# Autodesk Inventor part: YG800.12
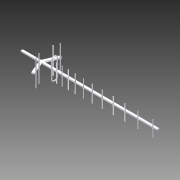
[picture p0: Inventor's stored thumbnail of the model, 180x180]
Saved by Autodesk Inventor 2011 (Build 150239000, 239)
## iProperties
Created: 2014-03
Part Number: YG800.12
Document SubType Name: Modeling
Designer: Evgeny
Density: 1 g/cm^3
Author: Evgeny
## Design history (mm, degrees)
sketch "Эскиз1"
  geometry: C1 r 4 at (0, 0); C2 r 3 at (0, 0); C3 r 4 at (80, 0); C4 r 3 at (80, 0); C5 r 4 at (125, 0); C6 r 3 at (125, 0); C7 r 4 at (172, 0); C8 r 3 at (172, 0); C9 r 4 at (226, 0); C10 r 3 at (226, 0); C11 r 4 at (288.5, 0); C12 r 3 at (288.5, 0); C13 r 4 at (359.5, 0); C14 r 3 at (359.5, 0); C15 r 4 at (438.5, 0); C16 r 3 at (438.5, 0); C17 r 4 at (525.5, 0); C18 r 3 at (525.5, 0); C19 r 4 at (725.5, 0); C20 r 3 at (725.5, 0); C21 r 4 at (621.5, 0); C22 r 3 at (621.5, 0); C23 r 4 at (35, 95); C24 r 3 at (35, 95); C25 r 4 at (35, -95); C26 r 3 at (35, -95); C27 r 3 at (837.5, 0); C28 r 4 at (837.5, 0); C29 r 3 at (969, 0); C30 r 4 at (969, 0); 1 further point
  constraints: 30 centre point, 16 coincident
  dimensions: "d0" = 8 diameter of C1; "d1" = 6 diameter of C2; "d2" = 8 diameter of C3; "d3" = 6 diameter of C4; "d4" = 8 diameter of C5; "d5" = 6 diameter of C6; "d6" = 8 diameter of C7; "d7" = 6 diameter of C8; "d8" = 8 diameter of C9; "d9" = 6 diameter of C10; "d10" = 8 diameter of C11; "d11" = 6 diameter of C12; "d12" = 8 diameter of C13; "d13" = 6 diameter of C14; "d14" = 8 diameter of C15; "d15" = 6 diameter of C16; "d16" = 8 diameter of C17; "d17" = 6 diameter of C18; "d18" = 8 diameter of C19; "d19" = 6 diameter of C20; "d20" = 8 diameter of C21; "d21" = 6 diameter of C22; "d22" = 8 diameter of C23; "d23" = 6 diameter of C24; "d24" = 8 diameter of C25; "d25" = 6 diameter of C26; "d26" = 35 horizontal distance of point (0, 0) C23.centre; "d27" = 35 horizontal distance of C25.centre C1.centre; "d28" = 95 vertical distance of point (0, 0) C24.centre; "d29" = 95 vertical distance of point (0, 0) C25.centre; "d30" = 80 distance of C3.centre point (0, 0); "d31" = 125 distance of C5.centre point (0, 0); "d32" = 172 distance of C7.centre point (0, 0); "d33" = 226 distance of point (0, 0) C9.centre; "d34" = 288.5 distance of point (0, 0) C11.centre; "d35" = 359.5 distance of point (0, 0) C13.centre; "d36" = 438.5 distance of point (0, 0) C15.centre; "d37" = 525.5 distance of point (0, 0) C17.centre; "d38" = 621.5 distance of point (0, 0) C21.centre; "d39" = 725.5 distance of point (0, 0) C19.centre; "d40" = 8 diameter of C28; "d41" = 6 diameter of C27; "d42" = 8 diameter of C30; "d43" = 6 diameter of C29; "d46" = 837.5 distance of point (0, 0) C28.centre; "d47" = 969 distance of point (0, 0) C30.centre
extrude "Выдавливание2" join sketch "Эскиз1" stored distance "d50" = 159; taper "d51" = 0 deg
extrude "Выдавливание3" join sketch "Эскиз1" stored distance "d52" = 156.5; taper "d53" = 0 deg
extrude "Выдавливание4" join sketch "Эскиз1" stored distance "d54" = 154; taper "d55" = 0 deg
extrude "Выдавливание5" join sketch "Эскиз1" stored distance "d56" = 151.5; taper "d57" = 0 deg
extrude "Выдавливание6" join sketch "Эскиз1" stored distance "d58" = 149; taper "d59" = 0 deg
extrude "Выдавливание7" join sketch "Эскиз1" stored distance "d60" = 146; taper "d61" = 0 deg
extrude "Выдавливание8" join sketch "Эскиз1" stored distance "d62" = 144; taper "d63" = 0 deg
extrude "Выдавливание9" join sketch "Эскиз1" stored distance "d64" = 141; taper "d65" = 0 deg
extrude "Выдавливание10" join sketch "Эскиз1" stored distance "d66" = 138; taper "d67" = 0 deg
extrude "Выдавливание11" join sketch "Эскиз1" stored distance "d68" = 135; taper "d69" = 0 deg
extrude "Выдавливание12" join sketch "Эскиз1" stored distance "d70" = 133; taper "d71" = 0 deg
node "РабПлоскость1"
sketch "Эскиз2"
  geometry: L1 (0.073, 69)-(0.073, -69); L2 (50.073, -69)-(50.073, -7); L3 (50.073, 69)-(50.073, 7); A1 r 25 centre (25.073, 69) between (50.073, 69) and (0.073, 69); A2 r 25 centre (25.073, -69) between (0.073, -69) and (50.073, -69); 1 further point
  constraints: 6 end point, 4 point on circle, 3 tangent, 2 centre point, 1 collinear, 1 parallel, 1 vertical
  dimensions: "d83" = 50 diameter of A1; "d84" = 50 diameter of A2; "d85" = 69 vertical distance of point (0, 0) A1.centre; "d86" = 138 distance of A2.centre A1.centre; "d87" = 50 distance between parallel lines of L2 L1; "d88" = 7 vertical distance of L3.end point (0, 0); "d89" = 14 distance of L2.end L3.end
feature "Сдвиг1" sketch "Эскиз2" dims "d90" = 0
sketch "Эскиз4"
  geometry: L1 (7, 6.5)-(27, 6.5); L2 (27, 6.5)-(27, -6.5); L3 (27, -6.5)-(7, -6.5); L4 (7, -6.5)-(7, 6.5); L5 (26, 5.5)-(8, 5.5); L6 (8, 5.5)-(8, -5.5); L7 (8, -5.5)-(26, -5.5); L8 (26, -5.5)-(26, 5.5); 1 further point
  constraints: 16 end point, 4 parallel, 2 horizontal, 2 perpendicular
  dimensions: "d91" = 7 distance from line of L4 point (0, 0); "d92" = 20 distance between parallel lines of L2 L4; "d93" = 13 distance between parallel lines of L1 L3; "d94" = 6.5 distance from line of L3 point (0, 0); "d95" = 1 distance between parallel lines of L4 L6; "d96" = 1 distance between parallel lines of L1 L5; "d97" = 1 distance between parallel lines of L8 L2; "d98" = 1 distance between parallel lines of L3 L7
extrude "Выдавливание13" join sketch "Эскиз4" distance "d99" = 1000; taper "d101" = 0 deg; dims "d100" = 200, "d102" = 0
sketch "Эскиз5"
  geometry: C1 r 2 at (235, -5.5); C2 r 2 at (280, -5.5); C3 r 2 at (325, -5.5); C4 r 2 at (372, -5.5); C5 r 2 at (426, -5.5); C6 r 2 at (488.5, -5.5); C7 r 2 at (559.5, -5.5); C8 r 2 at (638.5, -5); C9 r 2 at (725.5, -5.5); C10 r 2 at (821.5, -5.5); C11 r 2 at (925.5, -5); C12 r 2 at (1037.5, -5.5); C13 r 2 at (1169, -5); C14 r 2 at (200, -5.5); 1 further point
  constraints: 14 centre point, 1 coincident
  dimensions: "d104" = 4 diameter of C1; "d105" = 4 diameter of C2; "d106" = 4 diameter of C3; "d107" = 4 diameter of C4; "d108" = 4 diameter of C5; "d109" = 4 diameter of C6; "d110" = 4 diameter of C7; "d111" = 4 diameter of C8; "d112" = 4 diameter of C9; "d113" = 4 diameter of C10; "d114" = 4 diameter of C11; "d115" = 4 diameter of C12; "d116" = 4 diameter of C13; "d117" = 35 distance of C1.centre point (200, -5.5); "d118" = 45 distance of C2.centre C1.centre; "d119" = 45 distance of C3.centre C2.centre; "d120" = 47 distance of C4.centre C3.centre; "d121" = 54 distance of C5.centre C4.centre; "d122" = 62.5 distance of C6.centre C5.centre; "d123" = 71 distance of C7.centre C6.centre; "d124" = 79 horizontal distance of C8.centre C7.centre; "d125" = 87 horizontal distance of C9.centre C8.centre; "d126" = 96 distance of C10.centre C9.centre; "d127" = 104 horizontal distance of C11.centre C10.centre; "d128" = 112 horizontal distance of C12.centre C11.centre; "d129" = 131.5 horizontal distance of C13.centre C12.centre; "d161" = 4 diameter of C14
sketch "Эскиз6"
  geometry: L1 (157, -9)-(212, 119.744); L2 (212, 119.744)-(230.392, 111.887); L3 (230.392, 111.887)-(178.749, -9); L4 (178.749, -9)-(230.392, -129.887); L5 (230.392, -129.887)-(212, -137.744); L6 (212, -137.744)-(157, -9); 1 further point
  constraints: 12 end point, 2 parallel, 2 perpendicular
  dimensions: "d132" = 55 horizontal distance of L1.end L1.start; "d133" = 140 distance of L1.start L1.end; "d134" = 20 distance between parallel lines of L3 L1; "d135" = 140 distance of L5.end L1.start; "d136" = 55 horizontal distance of L5.end L1.start; "d137" = 20 distance between parallel lines of L4 L6; "d138" = 43 horizontal distance of point (200, -26) L1.start
extrude "Выдавливание15" join sketch "Эскиз6" distance "d139" = 13; taper "d140" = 0 deg
sketch "Эскиз7"
  geometry: L1 (-21.251, 17)-(30.392, 137.887) reference; L2 (30.392, 137.887)-(12, 145.744) reference; L3 (30.392, -103.887)-(-21.251, 17) reference; L4 (12, -111.744)-(30.392, -103.887) reference; C1 r 4 at (32.115, 124.102); C2 r 3 at (32.115, 124.102); C3 r 4 at (12.472, 78.122); C4 r 3 at (12.472, 78.122); C5 r 4 at (12.472, -44.122); C6 r 3 at (12.472, -44.122); C7 r 4 at (32.115, -90.102); C8 r 3 at (32.115, -90.102); 1 further point
  constraints: 8 centre point, 4 coincident
  dimensions: "d141" = 6 diameter of C2; "d142" = 8 diameter of C1; "d143" = 6 diameter of C4; "d144" = 8 diameter of C3; "d145" = 6 diameter of C6; "d146" = 8 diameter of C5; "d147" = 6 diameter of C8; "d148" = 8 diameter of C7; "d149" = 7 distance from line of C1.centre L1; "d150" = 7 distance from line of L1 C3.centre; "d151" = 12 distance from line of C1.centre L2; "d152" = 62 distance from line of C3.centre L2; "d153" = 7 distance from line of C7.centre L3; "d154" = 7 distance from line of C5.centre L3; "d155" = 12 distance from line of L4 C7.centre; "d156" = 62 distance from line of C5.centre L4
extrude "Выдавливание17" join sketch "Эскиз7" stored distance "d159" = 230; taper "d160" = 0 deg
extrude "Выдавливание18" join sketch "Эскиз5" distance "d162" = 14; taper "d163" = 0 deg
sketch "Эскиз8"
  geometry: L1 (0, 0)-(13, 0) reference; C1 r 2 at (6.5, 12); C2 r 2 at (6.5, 62); 1 further point
  constraints: 2 centre point
  dimensions: "d164" = 12 distance from line of C1.centre L1; "d165" = 62 distance from line of C2.centre L1; "d166" = 4 diameter of C1; "d167" = 4 diameter of C2
extrude "Выдавливание19" join sketch "Эскиз8" distance "d168" = 14; taper "d169" = 0 deg
sketch "Эскиз9"
  geometry: L1 (0, 0)-(13, 0) reference; C1 r 2 at (6.5, -12); C2 r 2 at (6.5, -62); 1 further point
  constraints: 2 centre point
  dimensions: "d170" = 4 diameter of C1; "d171" = 4 diameter of C2; "d172" = 12 distance from line of C1.centre L1; "d173" = 62 distance from line of C2.centre L1
extrude "Выдавливание20" join sketch "Эскиз9" distance "d174" = 14; taper "d175" = 0 deg
node "Твердое тело1"
